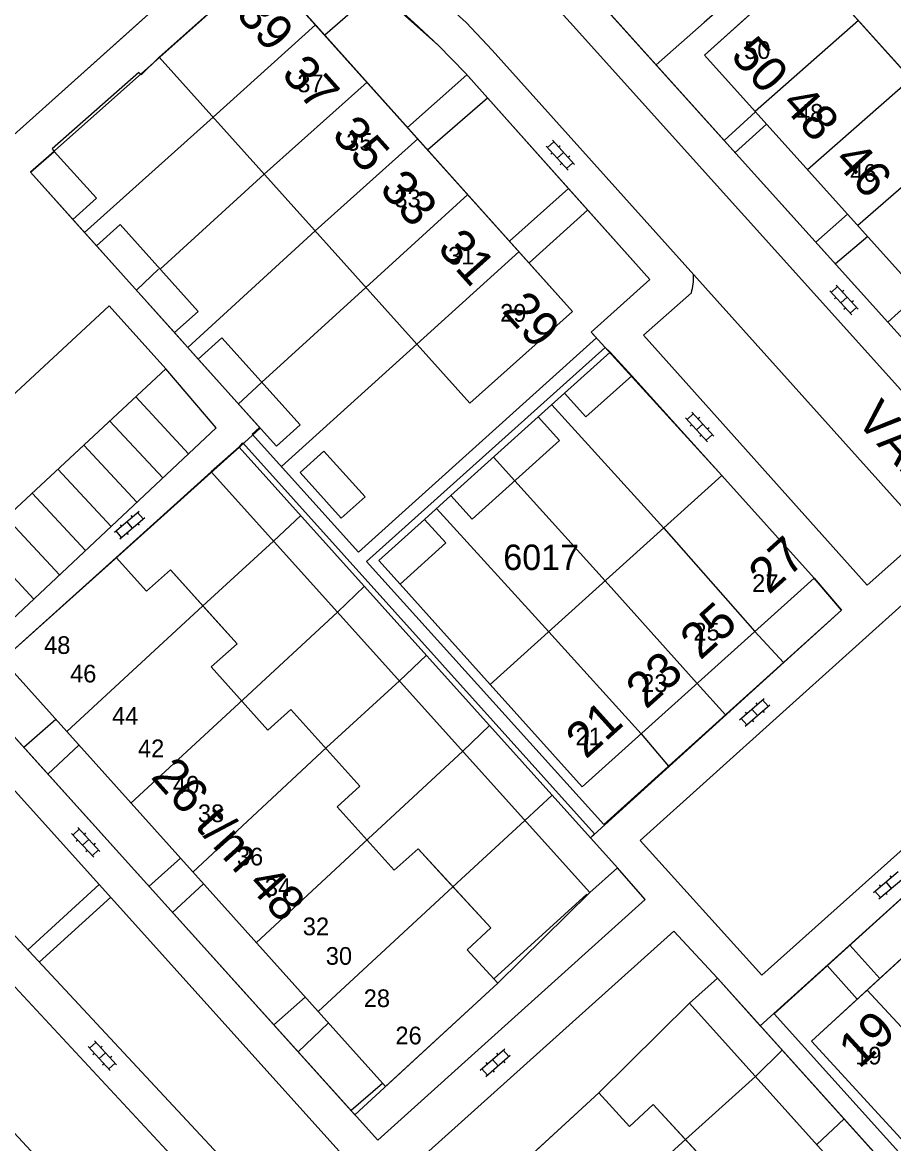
# Model space of a CAD drawing. Extents: x 148816 to 151297, y 399515 to 402500.
# Drawn here: x 150188.7 to 150250.3, y 399670.8 to 399750 of the extents above; entities that cross this region are included whole.
import ezdxf

# ---------------------------------------------------------------- set-up
doc = ezdxf.new("R2010")
doc.units = 0
for name, color, linetype in [('B01 Hoofdgebouw  [T] Norm', 7, 'Continuous'), ('B01 hoofgebouw', 7, 'Continuous'), ('B02 Bijgebouw  [D] Norm', 7, 'Continuous'), ('B07 Tussenmuur  [D] Norm', 7, 'Continuous'), ('G01 perceelsgrens', 7, 'Continuous'), ('S02 Open verharding  Norm', 7, 'Continuous'), ('T01 Muur  [D] Gem', 7, 'Continuous'), ('T04 Haag heg  [D] Gem', 7, 'Continuous'), ('V00 Kant verharding algemeen  [T] Norm', 7, 'Continuous'), ('V00 Kant verharding algemeen secundair  [T] Gem', 7, 'Continuous'), ('Z01 perceelnummer', 7, 'Continuous'), ('Z02 huisnummer', 7, 'Continuous'), ('Z02 Huisnummer  [Tekst] Norm', 7, 'Continuous'), ('Z06 straatnaam', 7, 'Continuous')]:
    doc.layers.add(name, color=color, linetype=linetype)

msp = doc.modelspace()

# ---------------------------------------------------------------- linework, layer by layer
at = {"layer": 'B01 Hoofdgebouw  [T] Norm'}
for p, q in [((150205.69, 399754.03), (150201.175, 399750)), ((150209.3, 399750), (150205.69, 399754.03)), ((150239.505, 399750), (150244.16, 399754.19)), ((150244.16, 399754.19), (150247.93, 399750)), ((150201.175, 399750), (150198.42, 399747.54)), ((150227.6, 399729.58), (150209.3, 399750)), ((150236.93, 399747.68), (150239.505, 399750)), ((150247.93, 399750), (150258.91, 399737.8)), ((150251.68, 399731.29), (150236.93, 399747.68)), ((150198.42, 399747.54), (150220.35, 399723.09)), ((150190.99, 399740.88), (150189.32, 399739.41)), ((150193.98, 399737.57), (150190.99, 399740.88)), ((150189.32, 399739.41), (150192.32, 399736.07)), ((150192.32, 399736.07), (150193.98, 399737.57)), ((150195.65, 399735.72), (150193.98, 399734.22)), ((150201.16, 399729.58), (150195.65, 399735.72)), ((150193.98, 399734.22), (150199.49, 399728.08)), ((150199.49, 399728.08), (150201.16, 399729.58)), ((150220.35, 399723.09), (150227.6, 399729.58)), ((150202.84, 399727.71), (150201.17, 399726.21)), ((150208.37, 399721.55), (150202.84, 399727.71)), ((150230.27, 399726.69), (150227.05, 399723.8)), ((150231.8, 399725.03), (150230.27, 399726.69)), ((150201.17, 399726.21), (150206.69, 399720.05)), ((150228.55, 399722.13), (150231.8, 399725.03)), ((150227.05, 399723.8), (150228.55, 399722.13)), ((150206.69, 399720.05), (150208.37, 399721.55)), ((150219.02, 399716.56), (150225.19, 399722.13)), ((150225.19, 399722.13), (150226.69, 399720.45)), ((150204.07, 399719.99), (150202.09, 399718.23)), ((150230.78, 399690.26), (150204.07, 399719.99)), ((150226.69, 399720.45), (150220.53, 399714.89)), ((150210.05, 399719.69), (150208.38, 399718.19)), ((150212.95, 399716.46), (150210.05, 399719.69)), ((150202.09, 399718.23), (150228.84, 399688.5)), ((150208.38, 399718.19), (150211.27, 399714.96)), ((150238.16, 399717.97), (150221.78, 399703.2)), ((150244.68, 399710.72), (150238.16, 399717.97)), ((150211.27, 399714.96), (150212.95, 399716.46)), ((150220.53, 399714.89), (150219.02, 399716.56)), ((150213.92, 399711.96), (150217.15, 399714.88)), ((150217.15, 399714.88), (150218.66, 399713.21)), ((150218.66, 399713.21), (150215.43, 399710.29)), ((150195.36, 399712.19), (150197.51, 399709.8)), ((150197.51, 399709.8), (150199.2, 399711.32)), ((150199.2, 399711.32), (150202.55, 399707.6)), ((150215.43, 399710.29), (150213.92, 399711.96)), ((150228.29, 399695.97), (150244.68, 399710.72)), ((150221.78, 399703.2), (150228.29, 399695.97)), ((150260.66, 399692.86), (150244.48, 399677.99)), ((150228.84, 399688.5), (150230.78, 399690.26)), ((150235.87, 399680.69), (150237.84, 399682.45)), ((150237.84, 399682.45), (150264.6, 399652.71)), ((150262.63, 399650.93), (150235.87, 399680.69)), ((150244.48, 399677.99), (150251.06, 399670.83))]:
    msp.add_line(p, q, dxfattribs=at)
for points in [[(150195.36, 399712.19), (150187.33, 399704.95), (150214.39, 399674.79), (150222.34, 399682.1), (150220.17, 399684.46), (150221.84, 399686), (150216.695, 399691.585), (150215.011, 399690.074), (150210.979, 399694.567), (150212.592, 399696.014), (150207.719, 399701.445), (150206.094, 399699.987), (150202.089, 399704.451), (150203.912, 399706.087), (150199.2, 399711.32), (150197.51, 399709.8), (150195.36, 399712.19)], [(150229.46, 399674.35), (150221.5, 399667.03), (150247.9, 399637.66), (150255.95, 399644.9), (150253.81, 399647.28), (150255.5, 399648.79), (150250.795, 399654.015), (150248.886, 399652.299), (150244.899, 399656.735), (150246.486, 399658.161), (150241.556, 399663.646), (150239.997, 399662.244), (150235.986, 399666.706), (150237.951, 399668.472), (150233.3, 399673.52), (150231.63, 399671.98), (150229.46, 399674.35)]]:
    msp.add_lwpolyline(points, dxfattribs=at)
at = {"layer": 'B01 hoofgebouw'}
for points in [[(150198.42, 399747.54), (150220.35, 399723.09), (150227.6, 399729.58), (150205.69, 399754.03), (150198.42, 399747.54)], [(150258.91, 399737.8), (150251.68, 399731.29), (150236.93, 399747.68), (150244.16, 399754.19), (150258.91, 399737.8)], [(150192.32, 399736.07), (150189.32, 399739.41), (150190.99, 399740.88), (150193.98, 399737.57), (150192.32, 399736.07)], [(150199.49, 399728.08), (150193.98, 399734.22), (150195.65, 399735.72), (150201.16, 399729.58), (150199.49, 399728.08)], [(150206.69, 399720.05), (150201.17, 399726.21), (150202.84, 399727.71), (150208.37, 399721.55), (150206.69, 399720.05)], [(150228.55, 399722.13), (150227.05, 399723.8), (150230.27, 399726.69), (150231.8, 399725.03), (150228.55, 399722.13)], [(150226.69, 399720.45), (150225.19, 399722.13), (150219.02, 399716.56), (150220.53, 399714.89), (150226.69, 399720.45)], [(150204.07, 399719.99), (150230.78, 399690.26), (150228.84, 399688.5), (150202.091, 399718.23), (150204.07, 399719.99)], [(150211.27, 399714.96), (150208.38, 399718.19), (150210.05, 399719.69), (150212.95, 399716.46), (150211.27, 399714.96)], [(150238.16, 399717.97), (150244.68, 399710.72), (150228.29, 399695.97), (150221.78, 399703.2), (150238.16, 399717.97)], [(150217.15, 399714.88), (150213.92, 399711.96), (150215.43, 399710.29), (150218.66, 399713.21), (150217.15, 399714.88)], [(150218.45, 399689.68), (150221.84, 399686), (150220.17, 399684.46), (150222.34, 399682.1), (150214.39, 399674.79), (150187.33, 399704.95), (150195.36, 399712.19), (150197.51, 399709.8), (150199.2, 399711.32), (150202.55, 399707.6)], [(150202.55, 399707.6), (150203.912, 399706.087), (150202.089, 399704.451), (150206.094, 399699.987), (150207.719, 399701.445), (150212.592, 399696.014), (150210.979, 399694.567), (150215.011, 399690.074), (150216.695, 399691.585), (150218.45, 399689.68)], [(150251.06, 399670.83), (150244.48, 399677.99), (150260.66, 399692.86), (150267.2, 399685.66), (150251.06, 399670.83)], [(150237.84, 399682.45), (150235.87, 399680.69), (150262.63, 399650.93), (150264.6, 399652.71), (150237.84, 399682.45)], [(150236.69, 399669.84), (150233.3, 399673.52), (150231.63, 399671.98), (150229.46, 399674.35), (150221.5, 399667.03), (150247.9, 399637.66), (150255.95, 399644.9), (150253.81, 399647.28), (150255.5, 399648.79), (150252.15, 399652.51)]]:
    msp.add_lwpolyline(points, dxfattribs=at)
at = {"layer": 'B02 Bijgebouw  [D] Norm'}
for p, q in [((150223.54, 399717.606), (150222.023, 399719.271)), ((150208.42, 399715.148), (150206.495, 399713.335)), ((150212.914, 399710.146), (150211.008, 399708.319)), ((150217.29, 399705.276), (150215.376, 399703.464)), ((150221.747, 399700.314), (150219.854, 399698.487)), ((150226.18, 399695.38), (150224.245, 399693.606)), ((150248.417, 399681.609), (150255.03, 399674.477)), ((150242.412, 399677.368), (150240.541, 399675.496)), ((150246.794, 399672.499), (150244.859, 399670.694))]:
    msp.add_line(p, q, dxfattribs=at)
for points in [[(150198.355, 399732.561), (150196.798, 399731.076)], [(150205.64, 399724.544), (150203.98, 399723.018)], [(150234.05, 399714.264), (150240.498, 399706.957)], [(150229.911, 399710.532), (150236.408, 399703.276)], [(150225.927, 399706.939), (150232.452, 399699.715)]]:
    msp.add_lwpolyline(points, dxfattribs=at)
at = {"layer": 'B07 Tussenmuur  [D] Norm'}
for p, q in [((150247.812, 399750.132), (150240.506, 399743.707)), ((150247.812, 399750.132), (150240.506, 399743.707)), ((150209.462, 399749.819), (150202.216, 399743.308)), ((150209.462, 399749.819), (150202.216, 399743.308)), ((150213.091, 399745.77), (150205.837, 399739.271)), ((150213.091, 399745.77), (150205.837, 399739.271)), ((150251.527, 399746.003), (150244.216, 399739.584)), ((150251.527, 399746.003), (150244.216, 399739.584)), ((150216.68, 399741.765), (150209.425, 399735.271)), ((150216.68, 399741.765), (150209.425, 399735.271)), ((150255.11, 399742.022), (150247.753, 399735.654)), ((150255.11, 399742.022), (150247.753, 399735.654)), ((150220.206, 399737.831), (150213.012, 399731.271)), ((150220.206, 399737.831), (150213.012, 399731.271)), ((150223.823, 399733.795), (150216.612, 399727.258)), ((150223.823, 399733.795), (150216.612, 399727.258)), ((150201.49, 399708.777), (150191.879, 399699.88)), ((150201.49, 399708.777), (150191.879, 399699.88)), ((150204.335, 399702.143), (150196.408, 399694.832)), ((150204.335, 399702.143), (150196.408, 399694.832)), ((150210.237, 399698.753), (150200.791, 399689.947)), ((150210.237, 399698.753), (150200.791, 399689.947)), ((150213.166, 399692.292), (150205.266, 399684.96)), ((150213.166, 399692.292), (150205.266, 399684.96)), ((150219.153, 399688.917), (150209.63, 399680.096)), ((150219.153, 399688.917), (150209.63, 399680.096)), ((150235.582, 399671.043), (150225.822, 399662.222)), ((150235.582, 399671.043), (150225.822, 399662.222))]:
    msp.add_line(p, q, dxfattribs=at)
at = {"layer": 'G01 perceelsgrens'}
for points in [[(150298.085, 399675.163), (150295.981, 399677.502), (150278.6, 399696.85), (150273.746, 399702.254), (150250.98, 399727.6), (150249.88, 399728.82), (150242.407, 399737.121), (150238.964, 399740.945), (150237.761, 399742.281), (150216.13, 399766.35), (150214.24, 399764.68), (150196.26, 399784.61)], [(150205.54, 399757.67), (150183.37, 399737.79), (150182.863, 399738.161), (150181.45, 399736.85), (150179.842, 399735.668), (150182.18, 399733.153)], [(150208.15, 399756.278), (150205.699, 399754.029), (150198.459, 399747.535), (150189.32, 399739.41), (150205.551, 399721.321), (150204.162, 399720.051), (150195.487, 399712.246), (150187.33, 399704.95), (150185.13, 399702.88), (150212.226, 399672.801)], [(150212.226, 399672.801), (150222.34, 399682.1), (150228.84, 399688.5), (150230.78, 399690.26), (150228.882, 399692.372), (150246.62, 399708.47), (150244.68, 399710.72), (150238.16, 399717.97), (150228.93, 399728.12), (150233.06, 399731.83), (150227.057, 399738.553), (150220.04, 399746.41), (150218.15, 399748.36), (150214.74, 399751.38)], [(150258.434, 399694.944), (150240.873, 399679.079), (150237.84, 399682.45), (150235.87, 399680.69), (150229.46, 399674.35), (150219.264, 399664.974)]]:
    msp.add_lwpolyline(points, dxfattribs=at)
at = {"layer": 'S02 Open verharding  Norm'}
for p, q in [((150225.846, 399741.151), (150226.289, 399741.556)), ((150226.188, 399741.667), (150227.739, 399739.968)), ((150225.745, 399741.262), (150227.296, 399739.563)), ((150226.183, 399740.782), (150226.073, 399740.681)), ((150226.964, 399740.817), (150226.52, 399740.413)), ((150226.737, 399741.288), (150226.627, 399741.187)), ((150227.411, 399740.549), (150227.301, 399740.448)), ((150226.857, 399740.043), (150226.747, 399739.942)), ((150227.195, 399739.674), (150227.638, 399740.079)), ((150245.783, 399731.034), (150247.334, 399729.335)), ((150245.884, 399730.923), (150246.327, 399731.328)), ((150246.226, 399731.439), (150247.777, 399729.74)), ((150246.775, 399731.06), (150246.665, 399730.959)), ((150246.221, 399730.554), (150246.111, 399730.453)), ((150247.002, 399730.589), (150246.558, 399730.185)), ((150247.449, 399730.321), (150247.339, 399730.22)), ((150246.895, 399729.815), (150246.785, 399729.714)), ((150247.233, 399729.446), (150247.676, 399729.851)), ((150235.701, 399721.945), (150236.144, 399722.35)), ((150236.043, 399722.461), (150237.594, 399720.762)), ((150235.6, 399722.056), (150237.151, 399720.357)), ((150236.038, 399721.576), (150235.928, 399721.475)), ((150236.819, 399721.611), (150236.375, 399721.207)), ((150236.592, 399722.082), (150236.482, 399721.981)), ((150236.712, 399720.837), (150236.602, 399720.736)), ((150237.05, 399720.468), (150237.493, 399720.873)), ((150237.266, 399721.343), (150237.156, 399721.242)), ((150195.248, 399713.964), (150196.996, 399715.458)), ((150197.272, 399714.905), (150196.882, 399715.361)), ((150195.638, 399713.508), (150197.386, 399715.002)), ((150195.645, 399714.5), (150195.742, 399714.386)), ((150196.122, 399714.711), (150196.512, 399714.255)), ((150196.405, 399715.15), (150196.502, 399715.036)), ((150196.892, 399714.58), (150196.989, 399714.466)), ((150195.752, 399713.605), (150195.362, 399714.061)), ((150196.132, 399713.93), (150196.229, 399713.816)), ((150239.415, 399700.71), (150241.149, 399702.22)), ((150239.809, 399700.258), (150241.543, 399701.768)), ((150240.561, 399701.907), (150240.659, 399701.794)), ((150241.43, 399701.669), (150241.036, 399702.122)), ((150239.806, 399701.25), (150239.905, 399701.137)), ((150240.282, 399701.465), (150240.676, 399701.013)), ((150241.053, 399701.341), (150241.152, 399701.228)), ((150239.922, 399700.356), (150239.528, 399700.809)), ((150240.299, 399700.684), (150240.397, 399700.571)), ((150192.325, 399692.576), (150192.766, 399692.983)), ((150192.664, 399693.093), (150194.225, 399691.404)), ((150192.223, 399692.686), (150193.784, 399690.997)), ((150192.664, 399692.209), (150192.554, 399692.107)), ((150193.444, 399692.249), (150193.004, 399691.841)), ((150193.215, 399692.718), (150193.105, 399692.616)), ((150193.343, 399691.474), (150193.233, 399691.372)), ((150193.682, 399691.107), (150194.123, 399691.514)), ((150193.894, 399691.983), (150193.784, 399691.881)), ((150248.862, 399688.512), (150250.622, 399689.992)), ((150249.248, 399688.052), (150251.008, 399689.532)), ((150249.263, 399689.045), (150249.359, 399688.93)), ((150249.742, 399689.252), (150250.128, 399688.792)), ((150250.028, 399689.688), (150250.125, 399689.573)), ((150249.363, 399688.149), (150248.976, 399688.608)), ((150249.745, 399688.471), (150249.842, 399688.356)), ((150193.497, 399677.507), (150193.937, 399677.915)), ((150193.835, 399678.025), (150195.397, 399676.337)), ((150193.395, 399677.617), (150194.957, 399675.929)), ((150193.836, 399677.14), (150193.726, 399677.038)), ((150194.616, 399677.181), (150194.176, 399676.773)), ((150194.387, 399677.65), (150194.276, 399677.548)), ((150221.088, 399675.95), (150222.822, 399677.46)), ((150222.234, 399677.147), (150222.332, 399677.034)), ((150223.103, 399676.909), (150222.709, 399677.362)), ((150194.516, 399676.406), (150194.405, 399676.304)), ((150194.855, 399676.039), (150195.295, 399676.447)), ((150195.066, 399676.916), (150194.956, 399676.814)), ((150221.479, 399676.49), (150221.578, 399676.377)), ((150221.482, 399675.498), (150223.216, 399677.008)), ((150221.955, 399676.705), (150222.349, 399676.253)), ((150222.726, 399676.581), (150222.825, 399676.468)), ((150221.595, 399675.596), (150221.201, 399676.049)), ((150221.972, 399675.924), (150222.07, 399675.811))]:
    msp.add_line(p, q, dxfattribs=at)
at = {"layer": 'T01 Muur  [D] Gem'}
msp.add_arc((146462.144, 395971.338), 5231.629, 43.799522, 45.739922, dxfattribs=at)
at = {"layer": 'T04 Haag heg  [D] Gem'}
for p, q in [((150253.381, 399764.472), (150236.912, 399750)), ((150236.912, 399750), (150233.514, 399746.997)), ((150202.216, 399743.308), (150193.143, 399735.153)), ((150205.837, 399739.271), (150198.476, 399732.571)), ((150209.425, 399735.271), (150200.437, 399727.026)), ((150213.012, 399731.271), (150205.655, 399724.574)), ((150216.612, 399727.258), (150207.044, 399718.617)), ((150234.05, 399714.264), (150226.139, 399722.982)), ((150229.911, 399710.532), (150223.54, 399717.606)), ((150225.927, 399706.939), (150218.001, 399715.644)), ((150206.495, 399713.335), (150201.49, 399708.777)), ((150211.008, 399708.319), (150204.335, 399702.143)), ((150240.498, 399706.957), (150242.513, 399704.766)), ((150215.376, 399703.464), (150210.237, 399698.753)), ((150236.408, 399703.276), (150238.407, 399701.063)), ((150232.452, 399699.715), (150234.393, 399697.444)), ((150219.854, 399698.487), (150213.166, 399692.292)), ((150224.245, 399693.606), (150219.153, 399688.917)), ((150228.612, 399688.39), (150222.06, 399682.404)), ((150214.184, 399675.019), (150211.966, 399673.092)), ((150240.541, 399675.496), (150235.582, 399671.043))]:
    msp.add_line(p, q, dxfattribs=at)
msp.add_lwpolyline([(150235.87, 399680.69), (150229.46, 399674.35)], dxfattribs=at)
at = {"layer": 'V00 Kant verharding algemeen  [T] Norm'}
for p, q in [((150217.38, 399764.92), (150230.81, 399750)), ((150196.985, 399750), (150205.54, 399757.67)), ((150223.87, 399753.97), (150227.44, 399750)), ((150213.724, 399752.252), (150210.104, 399749.103)), ((150217.82, 399752.08), (150220.097, 399750)), ((150215.48, 399750.82), (150216.393, 399750)), ((150183.37, 399737.79), (150196.985, 399750)), ((150216.393, 399750), (150218.15, 399748.36)), ((150220.097, 399750), (150221.94, 399748.03)), ((150227.44, 399750), (150298.24, 399671.24)), ((150230.81, 399750), (150249.88, 399728.82)), ((150218.15, 399748.36), (150220.04, 399746.41)), ((150221.94, 399748.03), (150293.15, 399668.63)), ((150198.42, 399747.54), (150197.13, 399746.3)), ((150196.98, 399746.46), (150190.86, 399741.06)), ((150197.13, 399746.3), (150196.98, 399746.46)), ((150215.959, 399742.57), (150220.152, 399746.285)), ((150220.04, 399746.41), (150233.06, 399731.83)), ((150249.88, 399728.82), (150269.13, 399746.16)), ((150217.373, 399740.992), (150221.599, 399744.664)), ((150238.319, 399741.66), (150240.526, 399743.684)), ((150241.322, 399742.8), (150239.088, 399740.807)), ((150205.47, 399663.28), (150133.02, 399741.19)), ((150190.86, 399741.06), (150190.99, 399740.88)), ((150223.164, 399734.53), (150227.32, 399738.258)), ((150228.672, 399736.743), (150224.536, 399732.999)), ((150206.21, 399652.08), (150127.88, 399736.46)), ((150192.32, 399736.07), (150193.98, 399734.22)), ((150247.039, 399736.447), (150244.795, 399734.468)), ((150248.468, 399734.859), (150246.182, 399732.928)), ((150233.06, 399731.83), (150228.93, 399728.12)), ((150169.04, 399706), (150194.87, 399729.97)), ((150194.87, 399729.97), (150198.89, 399725.52)), ((150199.49, 399728.08), (150201.17, 399726.21)), ((150228.93, 399728.12), (150229.31, 399727.72)), ((150229.31, 399727.72), (150212.49, 399712.57)), ((150213.06, 399711.9), (150229.91, 399727.02)), ((150229.91, 399727.02), (150230.27, 399726.69)), ((150198.89, 399725.52), (150186.647, 399714.132)), ((150238.16, 399717.97), (150231.8, 399725.03)), ((150204.98, 399720.91), (150205.5, 399721.38)), ((150212.49, 399712.57), (150204.98, 399720.91)), ((150204.07, 399719.99), (150204.32, 399720.28)), ((150204.32, 399720.28), (150229.17, 399692.65)), ((150202.09, 399718.23), (150195.36, 399712.19)), ((150229.82, 399693.32), (150213.06, 399711.9)), ((150244.68, 399710.72), (150246.62, 399708.47)), ((150252.44, 399710.24), (150232.39, 399692.19)), ((150246.62, 399708.47), (150229.82, 399693.32)), ((150211.96, 399669.3), (150180.1, 399704.71)), ((150185.13, 399702.88), (150213.85, 399671)), ((150191.104, 399700.744), (150188.847, 399698.754)), ((150240.99, 399682.67), (150261.08, 399700.67)), ((150174.84, 399699.8), (150207.2, 399665.05)), ((150192.731, 399698.931), (150190.545, 399696.869)), ((150258.57, 399695.09), (150241.85, 399679.94)), ((150229.17, 399692.65), (150228.89, 399692.38)), ((150232.39, 399692.19), (150240.99, 399682.67)), ((150199.911, 399690.927), (150197.686, 399688.942)), ((150232.75, 399688.02), (150230.78, 399690.26)), ((150189.12, 399684.466), (150194.178, 399689.064)), ((150201.531, 399689.122), (150199.346, 399687.1)), ((150189.927, 399683.578), (150194.985, 399688.176)), ((150213.85, 399671), (150232.75, 399688.02)), ((150234.77, 399685.78), (150215.84, 399668.78)), ((150237.84, 399682.45), (150234.77, 399685.78)), ((150249.308, 399682.427), (150247.198, 399684.786)), ((150247.727, 399680.974), (150245.6, 399683.338)), ((150208.718, 399681.112), (150206.511, 399679.146)), ((150241.85, 399679.94), (150258.24, 399661.77)), ((150210.359, 399679.282), (150208.222, 399677.248))]:
    msp.add_line(p, q, dxfattribs=at)
for points in [[(150251.761, 399713.204), (150248.429, 399710.233), (150232.622, 399727.888), (150236.004, 399730.885)], [(150180.276, 399708.207), (150184.12, 399704.14), (150202.432, 399721.358), (150198.89, 399725.52)], [(150227.05, 399723.8), (150225.19, 399722.13)], [(150219.02, 399716.56), (150217.15, 399714.88)], [(150215.43, 399710.29), (150221.78, 399703.2)]]:
    msp.add_lwpolyline(points, dxfattribs=at)
msp.add_arc((150231.804, 399732.033), 4.354, 344.71091, 1.92463, dxfattribs=at)
at = {"layer": 'V00 Kant verharding algemeen secundair  [T] Gem'}
for p, q in [((150196.75, 399723.53), (150200.478, 399719.521)), ((150194.92, 399721.827), (150198.657, 399717.809)), ((150193.089, 399720.124), (150196.835, 399716.096)), ((150191.258, 399718.422), (150195.014, 399714.383)), ((150189.428, 399716.719), (150193.193, 399712.671)), ((150187.597, 399715.017), (150191.372, 399710.958)), ((150185.766, 399713.314), (150189.55, 399709.245))]:
    msp.add_line(p, q, dxfattribs=at)

# ---------------------------------------------------------------- texts
at = {"layer": 'Z01 perceelnummer'}
msp.add_text('6017', height=1.8, dxfattribs=at).set_placement((150222.718, 399711.298))
at = {"layer": 'Z02 huisnummer'}
for s, rotation, p in [('39', 311.83815, (150203.766, 399750.555)), ('50', 311.99999, (150238.697, 399747.581)), ('37', 311.88081, (150206.972, 399746.29)), ('48', 311.99999, (150242.281, 399744.177)), ('35', 311.88081, (150210.531, 399741.998)), ('46', 311.99999, (150246.008, 399740.193)), ('33', 311.88081, (150213.901, 399738.169)), ('31', 311.88081, (150217.993, 399733.991)), ('29', 311.88081, (150222.562, 399729.58)), ('27', 41.99999, (150241.475, 399709.516)), ('25', 41.99999, (150236.636, 399704.883)), ('23', 41.99999, (150232.805, 399701.407)), ('21', 41.99999, (150228.554, 399697.888)), ('26 t/m 48', 311.88081, (150197.757, 399696.649)), ('19', 42.609, (150247.852, 399675.995))]:
    msp.add_text(s, height=2.5, rotation=rotation, dxfattribs=at).set_placement(p)
at = {"layer": 'Z02 Huisnummer  [Tekst] Norm'}
for s, p in [('50', (150239.732, 399747.419)), ('48', (150243.464, 399742.986)), ('46', (150247.227, 399738.735)), ('27', (150240.298, 399709.741)), ('25', (150236.147, 399706.314)), ('48', (150190.277, 399705.368)), ('46', (150192.112, 399703.352)), ('23', (150232.457, 399702.678)), ('44', (150195.076, 399700.363)), ('21', (150227.82, 399698.91)), ('42', (150196.911, 399698.068)), ('40', (150199.38, 399695.496)), ('38', (150201.144, 399693.48)), ('36', (150203.896, 399690.421)), ('34', (150205.872, 399688.266)), ('32', (150208.554, 399685.485)), ('30', (150210.177, 399683.399)), ('28', (150212.858, 399680.409)), ('26', (150215.096, 399677.775)), ('19', (150247.58, 399676.355))]:
    msp.add_text(s, height=1.25, dxfattribs=at).set_placement(p)
for s, p in [('37', (150208.171, 399745.064)), ('35', (150211.621, 399740.935)), ('33', (150215.026, 399736.935)), ('31', (150218.825, 399732.891)), ('29', (150222.492, 399728.848))]:
    msp.add_text(s, height=1.25, rotation=0.02296, dxfattribs=at).set_placement(p)
at = {"layer": 'Z06 straatnaam'}
msp.add_text('VAN LEEUWENSTRAAT', height=2.5, rotation=311.91906, dxfattribs=at).set_placement((150247.554, 399721.863))

doc.saveas('drawing.dxf')
